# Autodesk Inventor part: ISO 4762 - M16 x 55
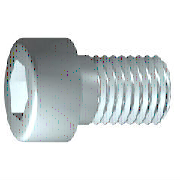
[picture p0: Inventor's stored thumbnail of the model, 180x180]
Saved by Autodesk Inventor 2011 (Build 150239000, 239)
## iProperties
Created: 2010-02
Part Number: ISO 4762 - M16 x 55
Material: Stainless Steel, 440C
Description: Hexagon Socket Head Cap Screw
Document SubType Name: Modeling
Standard: ISO 4762
Designer: 129877
Standard Revision: Fourth edition 2004-03-01
Standards Organization: ISO
Language: en-US
Size Designation: M16 x 55
Categories: <MemberInstance><Categories><Category DisplayName="Fasteners" InternalName="e4da775c-781d-43d5-af7c-5136215cf5a6" Mnemonic="FSTN"><Category DisplayName="Bolts"
Density: 7.75 g/cm^3
Mass: 128.28 g
Surface Area: 52.1677 cm^2
Volume: 16.5522 cm^3
IsCustomPart: 0
Author: 129877
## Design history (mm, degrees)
body "Solid1"
workplane "Work Plane1"
fillet "Fillet2" dims "d30" = 0.1 (= R)
revolve "Body" stored, may be unused: angle "d10" = 90 deg
sketch "Sketch2"
  geometry: L1 (0, -16.8)-(0, 16.8) reference; L2 (-16.8, 0)-(16.8, 0) reference; L3 (8.083, 0)-(4.041, -7); L4 (4.041, -7)-(-4.041, -7); L5 (-4.041, -7)-(-8.083, 0); L6 (-8.083, 0)-(-4.041, 7); L7 (-4.041, 7)-(4.041, 7); L8 (4.041, 7)-(8.083, 0); 2 further points
  constraints: 12 end point, 1 coincident, 1 horizontal alignment, 1 point on line, 12 other
extrude "Slot" join sketch "Sketch2" stored distance "d11" = 10; taper "d12" = 0 deg
fillet "Fillet1" dims "d17" = 1.6 (= RR)
feature "Thread" dims "d13" = 50 (= GEL), "d14" = 0
chamfer "Chamfer1" distance "d15" = 1.2269 (= -0.5 x SPD + 0.5 x GD); stored, may be unused: second distance "d16" = 1.2269 (= GUL), angle "d27" = 45 deg
sketch "Sketch1"
  geometry: L1 (-3.333, 0)-(55, 0); L2 (55, 0)-(55, 8); L3 (55, 8)-(5, 8); L4 (5, 8)-(3.773, 8); L5 (3.773, 8)-(0, 8); L6 (0, 8)-(0, 12); L7 (0, 12)-(-16, 12); L8 (-16, 12)-(-16, 8.083); L9 (-16, 8.083)-(-8, 8.083); L10 (-8, 8.083)-(-3.333, 0); L11 (-30.2, 0)-(69.2, 0) reference; L12 (0, -2.4)-(0, 14.4) reference; L13 (5, 8)-(0, 8)
  constraints: 22 end point, 6 parallel, 2 collinear, 2 perpendicular, 1 horizontal, 1 point on line
  dimensions: "d1" = 50 distance from line of L3.end L2 (= GEL); "d2" = 1.227 distance of L4.end L3.end (computed from GAL); "d3" = 16 distance between parallel lines of L8 L6 (= KOH); "d4" = 8 distance of L8.end L9.end (= INTI); "d5" = 60 deg angle of L10 L1; "d6" = 16 diameter of L3 L1 (= GD); "d7" = 16 diameter of L5 L1 (= BDM); "d8" = 16.16581 diameter of L9 L1 (= 1.1547 x SW); "d9" = 24 diameter of L7 L1 (= KOD); "d26" = 55 distance between parallel lines of L12 L2 (= NLG)
other parameters: "GD" = 16 [user parameter; used in 2 equation terms], "NLG" = 55 [user parameter; used in 1 equation term], "GEL" = 50 [user parameter; used in 2 equation terms], "KOD" = 24 [user parameter; used in 1 equation term], "KOH" = 16 [user parameter; used in 1 equation term], "INTI" = 8 [user parameter; used in 1 equation term], "GAL" = 1.2269 (= 0.61345 x PTC) [user parameter; used in 1 equation term], "GUL" = 1.2269 (= 0.61345 x PTC) [user parameter; used in 1 equation term], "BDM" = 16 (= NND) [user parameter; used in 1 equation term], "SW" = 14 [user parameter; used in 2 equation terms], "RR" = 1.6 [user parameter; used in 1 equation term], "SPD" = 13.5462 (= NND - 1.2269 x PTC) [user parameter; used in 1 equation term], "d19" = 0, "d28" = 0, "d29" = 0, "R" = 0.1 [user parameter; used in 1 equation term], "TOA" = 30 deg [user parameter], "GD1" = 13.5462 (= THREADDIA - 1.2269 x PTC) [user parameter], "THREADDIA" = 16 [user parameter; used in 1 equation term], "FAWI" = 45 deg [user parameter], "TPU" = 5 (computed from PTC) [user parameter], "PTC" = 2 [user parameter; used in 5 equation terms], "NND" = 16 [user parameter; used in 2 equation terms], "E0" = 16.17 (= 1.155 x SW) [user parameter]
